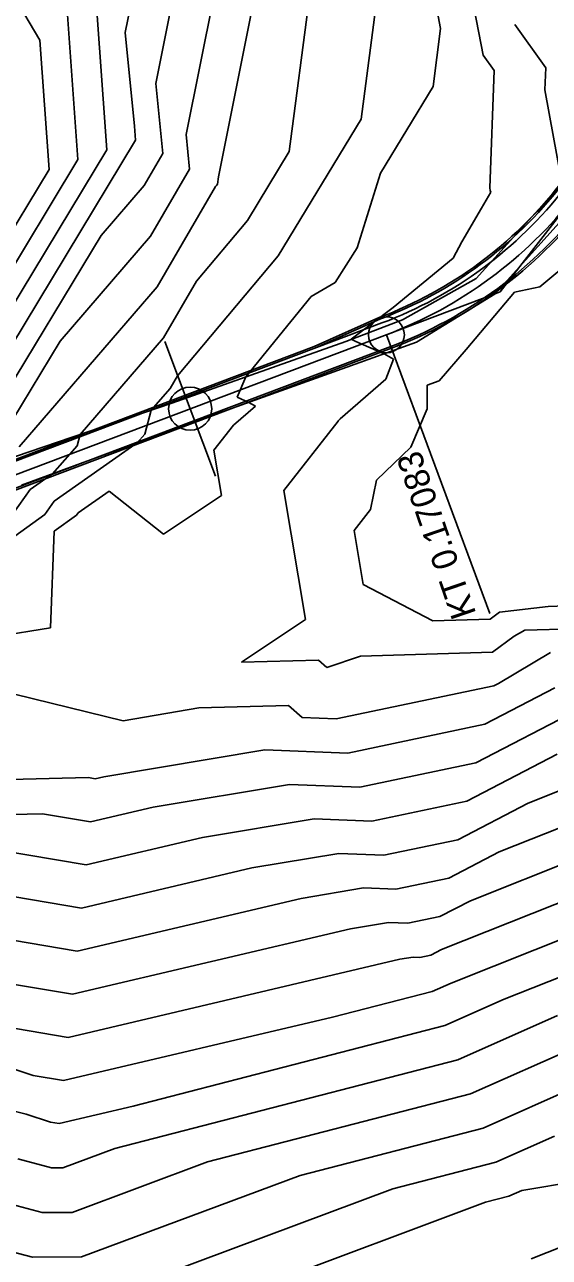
# Model space of a CAD drawing. Extents: x -549394 to -546608, y -1037055 to -1033629.
# Drawn here: x -547813.1 to -547740.1, y -1035648 to -1035476.6 of the extents above; entities that cross this region are included whole.
import ezdxf

# ---------------------------------------------------------------- set-up
doc = ezdxf.new("R2010")
doc.units = 0
for name, color, linetype in [('hlavni_vrst', 7, 'Continuous'), ('hrana_L', 7, 'Continuous'), ('norm_vrst', 7, 'Continuous'), ('POLYGONY_SITUACE_PO', 7, 'Continuous'), ('u_sirka_1_0m', 7, 'Continuous'), ('x_navrh_C11', 7, 'Continuous'), ('x_osa_C11', 7, 'Continuous'), ('x_popis_oblouky_C11', 7, 'Continuous'), ('x_popis_pricne_rezy_C11', 7, 'Continuous')]:
    doc.layers.add(name, color=color, linetype=linetype)

msp = doc.modelspace()

# ---------------------------------------------------------------- linework, layer by layer
at = {"layer": 'hlavni_vrst'}
for p, q in [((-547790.65, -1035491.85), (-547783.83, -1035457.7)), ((-547811, -1035478.7), (-547823.09, -1035458.32)), ((-547749.32, -1035480.8), (-547751.45, -1035469.69)), ((-547809.72, -1035496.69), (-547811, -1035478.7)), ((-547747.81, -1035482.91), (-547749.32, -1035480.8)), ((-547748.4, -1035499.26), (-547747.81, -1035482.91)), ((-547790.17, -1035496.66), (-547790.65, -1035491.85)), ((-547824.74, -1035521.56), (-547809.72, -1035496.69)), ((-547795.6, -1035505.97), (-547790.17, -1035496.66)), ((-547748.33, -1035499.63), (-547748.4, -1035499.26)), ((-547749.57, -1035502.06), (-547748.25, -1035499.85)), ((-547748.25, -1035499.85), (-547748.33, -1035499.63)), ((-547752.3, -1035506.77), (-547749.57, -1035502.06)), ((-547808.19, -1035520.58), (-547795.6, -1035505.97)), ((-547753.52, -1035509.03), (-547752.3, -1035506.77)), ((-547761.86, -1035515.87), (-547753.52, -1035509.03)), ((-547767.68, -1035520.31), (-547761.86, -1035515.87)), ((-547816.24, -1035533.92), (-547808.19, -1035520.58)), ((-547767.04, -1035520.62), (-547767.68, -1035520.31)), ((-547763.11, -1035522.34), (-547767.04, -1035520.62)), ((-547761.78, -1035523.07), (-547763.11, -1035522.34)), ((-547762.85, -1035525.84), (-547761.78, -1035523.07)), ((-547769.24, -1035531.38), (-547762.85, -1035525.84)), ((-547777.04, -1035541.33), (-547769.48, -1035531.68)), ((-547769.48, -1035531.68), (-547769.46, -1035531.6)), ((-547769.46, -1035531.6), (-547769.24, -1035531.38)), ((-547774.03, -1035559.28), (-547777.04, -1035541.33)), ((-547782.94, -1035565.21), (-547774.03, -1035559.28)), ((-547743.54, -1035560.76), (-547744.99, -1035561.61)), ((-547736.73, -1035560.59), (-547743.54, -1035560.76)), ((-547744.99, -1035561.61), (-547748.04, -1035563.85)), ((-547766.41, -1035564.39), (-547771.06, -1035565.95)), ((-547748.04, -1035563.85), (-547766.41, -1035564.39)), ((-547772.23, -1035564.94), (-547782.94, -1035565.21)), ((-547771.06, -1035565.95), (-547772.23, -1035564.94)), ((-547733.09, -1035580.87), (-547743.07, -1035584.83)), ((-547743.07, -1035584.83), (-547752.85, -1035589.91)), ((-547752.85, -1035589.91), (-547763.14, -1035592.07)), ((-547769.4, -1035591.83), (-547781.52, -1035593.85)), ((-547763.14, -1035592.07), (-547769.4, -1035591.83)), ((-547781.52, -1035593.85), (-547805.21, -1035599.43)), ((-547805.21, -1035599.43), (-547821.72, -1035596.64)), ((-547731.51, -1035606.21), (-547746.38, -1035612.11)), ((-547746.38, -1035612.11), (-547754.65, -1035615.77)), ((-547754.65, -1035615.77), (-547798.04, -1035626.99)), ((-547812.93, -1035628.1), (-547830.53, -1035623.58)), ((-547798.04, -1035626.99), (-547808.34, -1035629.41)), ((-547809.51, -1035629.21), (-547812.93, -1035628.1)), ((-547808.34, -1035629.41), (-547809.51, -1035629.21)), ((-547719.52, -1035634.57), (-547743.94, -1035638.7)), ((-547745.77, -1035639.51), (-547748.99, -1035640.35)), ((-547743.94, -1035638.7), (-547745.77, -1035639.51)), ((-547748.99, -1035640.35), (-547794.29, -1035657.24))]:
    msp.add_line(p, q, dxfattribs=at)
at = {"layer": 'hrana_L'}
for p, q in [((-547742.1, -1035502.76), (-547737.85, -1035498.19)), ((-547747.65, -1035514.01), (-547735.19, -1035500.12)), ((-547742.1, -1035502.76), (-547750.28, -1035511.84)), ((-547750.28, -1035511.84), (-547760.56, -1035517.59)), ((-547758.6, -1035520.72), (-547747.65, -1035514.01)), ((-547760.56, -1035517.59), (-547768.45, -1035520.6)), ((-547768.45, -1035520.6), (-547792.64, -1035529.21)), ((-547792.07, -1035532.74), (-547758.6, -1035520.72)), ((-547814.39, -1035536.61), (-547792.64, -1035529.21)), ((-547813.58, -1035540.62), (-547792.07, -1035532.74))]:
    msp.add_line(p, q, dxfattribs=at)
at = {"layer": 'norm_vrst'}
for p, q in [((-547776.3, -1035494.2), (-547770.68, -1035451.11)), ((-547786.17, -1035497.73), (-547777.32, -1035453.46)), ((-547794.89, -1035484.75), (-547790.33, -1035461.94)), ((-547755.25, -1035477.11), (-547757.91, -1035463.26)), ((-547766.3, -1035489.69), (-547762.97, -1035464.11)), ((-547799.13, -1035477.64), (-547796.84, -1035466.18)), ((-547801.69, -1035493.96), (-547803.35, -1035470.67)), ((-547805.71, -1035495.32), (-547807.19, -1035474.56)), ((-547740.62, -1035482.57), (-547744.92, -1035476.55)), ((-547797.82, -1035490.68), (-547799.13, -1035477.64)), ((-547756.3, -1035485.17), (-547755.25, -1035477.11)), ((-547740.73, -1035485.63), (-547740.62, -1035482.57)), ((-547793.91, -1035494.47), (-547794.89, -1035484.75)), ((-547763.62, -1035497.22), (-547756.3, -1035485.17)), ((-547738.44, -1035498.27), (-547740.73, -1035485.63)), ((-547797.68, -1035492.6), (-547797.82, -1035490.68)), ((-547777.85, -1035508.7), (-547766.3, -1035489.69)), ((-547821.34, -1035526.5), (-547801.69, -1035493.96)), ((-547819.64, -1035528.97), (-547797.68, -1035492.6)), ((-547782.13, -1035503.8), (-547776.3, -1035494.2)), ((-547823.04, -1035524.03), (-547805.71, -1035495.32)), ((-547796.5, -1035498.91), (-547793.91, -1035494.47)), ((-547766.88, -1035507.59), (-547763.62, -1035497.22)), ((-547802.5, -1035505.87), (-547796.5, -1035498.91)), ((-547794.7, -1035513.03), (-547786.55, -1035499.07)), ((-547786.55, -1035499.07), (-547786.41, -1035498.91)), ((-547786.41, -1035498.91), (-547786.3, -1035498.72)), ((-547786.3, -1035498.72), (-547786.17, -1035497.73)), ((-547789.21, -1035512.23), (-547782.13, -1035503.8)), ((-547817.94, -1035531.44), (-547802.5, -1035505.87)), ((-547769.91, -1035512.42), (-547766.88, -1035507.59)), ((-547791.87, -1035525.39), (-547777.85, -1035508.7)), ((-547741.46, -1035513.02), (-547738.65, -1035510.72)), ((-547813.88, -1035535.29), (-547794.7, -1035513.03)), ((-547793.8, -1035520.1), (-547789.21, -1035512.23)), ((-547773.24, -1035514.34), (-547769.91, -1035512.42)), ((-547744.97, -1035513.78), (-547741.46, -1035513.02)), ((-547782.36, -1035525.55), (-547773.24, -1035514.34)), ((-547751.7, -1035521.73), (-547744.97, -1035513.78)), ((-547805.39, -1035533.55), (-547793.8, -1035520.1)), ((-547755.46, -1035526.11), (-547751.7, -1035521.73)), ((-547792.9, -1035527.16), (-547791.87, -1035525.39)), ((-547783.57, -1035528.37), (-547782.36, -1035525.55)), ((-547757.14, -1035526.68), (-547755.46, -1035526.11)), ((-547757.11, -1035529.99), (-547757.14, -1035526.68)), ((-547795.51, -1035530.19), (-547792.9, -1035527.16)), ((-547781.92, -1035529.09), (-547783.57, -1035528.37)), ((-547796.4, -1035533.49), (-547795.51, -1035530.19)), ((-547784.08, -1035532.27), (-547780.99, -1035529.6)), ((-547780.99, -1035529.6), (-547781.92, -1035529.09)), ((-547759.4, -1035535.33), (-547757.11, -1035529.99)), ((-547805.82, -1035535.12), (-547805.39, -1035533.55)), ((-547797.48, -1035534.72), (-547796.4, -1035533.49)), ((-547786.8, -1035535.75), (-547784.08, -1035532.27)), ((-547809.23, -1035539.03), (-547805.82, -1035535.12)), ((-547809.01, -1035542.84), (-547797.48, -1035534.72)), ((-547764.16, -1035539.9), (-547759.4, -1035535.33)), ((-547785.74, -1035542.05), (-547786.8, -1035535.75)), ((-547812.35, -1035541.22), (-547809.23, -1035539.03)), ((-547765, -1035544.01), (-547764.16, -1035539.9)), ((-547814.73, -1035544.55), (-547812.35, -1035541.22)), ((-547805.68, -1035544.47), (-547801.37, -1035541.43)), ((-547801.37, -1035541.43), (-547793.79, -1035547.41)), ((-547793.79, -1035547.41), (-547785.74, -1035542.05)), ((-547810.32, -1035544.67), (-547809.01, -1035542.84)), ((-547821.28, -1035552.58), (-547810.32, -1035544.67)), ((-547809.01, -1035547.02), (-547805.91, -1035544.79)), ((-547805.91, -1035544.79), (-547805.68, -1035544.47)), ((-547767.28, -1035546.91), (-547765, -1035544.01)), ((-547809.54, -1035560.47), (-547809.01, -1035547.02)), ((-547766.02, -1035554.41), (-547767.28, -1035546.91)), ((-547756.31, -1035559.46), (-547766.02, -1035554.41)), ((-547740.3, -1035557.46), (-547747.06, -1035558.29)), ((-547737.81, -1035557.4), (-547740.3, -1035557.46)), ((-547748.34, -1035559.23), (-547756.31, -1035559.46)), ((-547747.06, -1035558.29), (-547748.34, -1035559.23)), ((-547824.52, -1035562.85), (-547809.54, -1035560.47)), ((-547739.94, -1035563.89), (-547747.21, -1035568.18)), ((-547799.43, -1035573.39), (-547821.16, -1035568.08)), ((-547747.85, -1035568.51), (-547769.8, -1035573.12)), ((-547739.33, -1035568.79), (-547749.1, -1035573.86)), ((-547747.21, -1035568.18), (-547747.85, -1035568.51)), ((-547776.43, -1035571.27), (-547788.87, -1035571.59)), ((-547774.49, -1035572.94), (-547776.43, -1035571.27)), ((-547735.03, -1035571.26), (-547750.35, -1035579.21)), ((-547788.87, -1035571.59), (-547799.43, -1035573.39)), ((-547769.8, -1035573.12), (-547774.49, -1035572.94)), ((-547749.1, -1035573.86), (-547768.14, -1035577.86)), ((-547779.72, -1035577.42), (-547802.13, -1035581.16)), ((-547768.14, -1035577.86), (-547779.72, -1035577.42)), ((-547739.05, -1035578.04), (-547751.6, -1035584.56)), ((-547750.35, -1035579.21), (-547766.47, -1035582.59)), ((-547804.25, -1035581.28), (-547834.2, -1035582)), ((-547803.33, -1035581.44), (-547804.25, -1035581.28)), ((-547802.13, -1035581.16), (-547803.33, -1035581.44)), ((-547776.28, -1035582.22), (-547795.26, -1035585.39)), ((-547766.47, -1035582.59), (-547776.28, -1035582.22)), ((-547751.6, -1035584.56), (-547764.81, -1035587.33)), ((-547810.63, -1035586.31), (-547829.92, -1035586.77)), ((-547803.96, -1035587.44), (-547810.63, -1035586.31)), ((-547795.26, -1035585.39), (-547803.96, -1035587.44)), ((-547732.77, -1035585.94), (-547747.09, -1035591.62)), ((-547772.84, -1035587.03), (-547788.39, -1035589.62)), ((-547764.81, -1035587.33), (-547772.84, -1035587.03)), ((-547788.39, -1035589.62), (-547804.58, -1035593.43)), ((-547804.58, -1035593.43), (-547817.01, -1035591.33)), ((-547747.09, -1035591.62), (-547754.1, -1035595.26)), ((-547732.46, -1035591.01), (-547751.11, -1035598.41)), ((-547754.1, -1035595.26), (-547761.47, -1035596.8)), ((-547765.96, -1035596.63), (-547774.64, -1035598.08)), ((-547761.47, -1035596.8), (-547765.96, -1035596.63)), ((-547732.14, -1035596.08), (-547755.13, -1035605.19)), ((-547774.64, -1035598.08), (-547805.84, -1035605.43)), ((-547751.11, -1035598.41), (-547755.35, -1035600.61)), ((-547762.52, -1035601.44), (-547767.77, -1035602.32)), ((-547759.81, -1035601.54), (-547762.52, -1035601.44)), ((-547755.35, -1035600.61), (-547759.81, -1035601.54)), ((-547731.82, -1035601.14), (-547753.78, -1035609.85)), ((-547805.84, -1035605.43), (-547819.27, -1035603.15)), ((-547767.77, -1035602.32), (-547806.46, -1035611.42)), ((-547755.13, -1035605.19), (-547756.6, -1035605.96)), ((-547760.9, -1035606.55), (-547807.09, -1035617.42)), ((-547759.08, -1035606.24), (-547760.9, -1035606.55)), ((-547758.14, -1035606.28), (-547759.08, -1035606.24)), ((-547756.6, -1035605.96), (-547758.14, -1035606.28)), ((-547806.46, -1035611.42), (-547816.83, -1035609.67)), ((-547753.78, -1035609.85), (-547756.42, -1035611.02)), ((-547756.42, -1035611.02), (-547770.3, -1035614.61)), ((-547770.3, -1035614.61), (-547807.72, -1035623.41)), ((-547738.98, -1035614.37), (-547752.87, -1035620.52)), ((-547807.09, -1035617.42), (-547814.39, -1035616.18)), ((-547731.58, -1035616.62), (-547751.1, -1035625.27)), ((-547811.95, -1035622.7), (-547824.38, -1035618.66)), ((-547752.87, -1035620.52), (-547800.58, -1035632.85)), ((-547807.72, -1035623.41), (-547811.95, -1035622.7)), ((-547734.91, -1035623.63), (-547749.32, -1035630.02)), ((-547751.1, -1035625.27), (-547787.68, -1035634.73)), ((-547749.32, -1035630.02), (-547774.79, -1035636.6)), ((-547739.42, -1035631.17), (-547747.54, -1035634.76)), ((-547800.58, -1035632.85), (-547807.79, -1035635.54)), ((-547809.39, -1035635.54), (-547814.08, -1035634.31)), ((-547787.68, -1035634.73), (-547806.51, -1035641.75)), ((-547747.54, -1035634.76), (-547761.89, -1035638.47)), ((-547807.79, -1035635.54), (-547809.39, -1035635.54)), ((-547774.79, -1035636.6), (-547805.23, -1035647.95)), ((-547810.7, -1035641.76), (-547822.95, -1035638.53)), ((-547761.89, -1035638.47), (-547803.95, -1035654.16)), ((-547812.01, -1035647.98), (-547831.81, -1035642.75)), ((-547806.51, -1035641.75), (-547810.7, -1035641.76)), ((-547729.59, -1035643.04), (-547742.66, -1035648.19)), ((-547805.23, -1035647.95), (-547812.01, -1035647.98))]:
    msp.add_line(p, q, dxfattribs=at)
at = {"layer": 'POLYGONY_SITUACE_PO'}
msp.add_circle((-547762.79, -1035519.68), 2.5, dxfattribs=at)
at = {"layer": 'u_sirka_1_0m'}
msp.add_circle((-547790.09, -1035529.97), 3, dxfattribs=at)
at = {"layer": 'x_navrh_C11'}
for p, q in [((-547763.41, -1035518.04), (-547833.94, -1035544.64)), ((-547763.72, -1035517.25), (-547772.86, -1035521.34)), ((-547763.62, -1035517.48), (-547772.77, -1035521.57)), ((-547762.18, -1035521.32), (-547832.71, -1035547.91)), ((-547772.86, -1035521.34), (-547824.66, -1035540.87)), ((-547762.09, -1035521.55), (-547820.66, -1035543.64))]:
    msp.add_line(p, q, dxfattribs=at)
for radius, start in [(57.4, 290.6532), (57.65, 290.6607), (58.25, 290.6607), (61.75, 290.6607), (62, 290.6607)]:
    msp.add_arc((-547783.96, -1035463.54), radius, start, 322.1652, dxfattribs=at)
at = {"layer": 'x_osa_C11'}
for points in [[(-547696.57, -1035442.62), (-547714.94, -1035472.48), (-547746.96, -1035513.71)], [(-547746.96, -1035513.71), (-547845.9, -1035551.02)]]:
    msp.add_lwpolyline(points, dxfattribs=at)
msp.add_arc((-547783.96, -1035463.54), 60, 290.6607, 322.1652, dxfattribs=at)
at = {"layer": 'x_popis_oblouky_C11'}
msp.add_lwpolyline([(-547762.79, -1035519.68), (-547748.42, -1035558.47)], dxfattribs=at)
at = {"layer": 'x_popis_pricne_rezy_C11'}
msp.add_lwpolyline([(-547786.56, -1035539.33), (-547790.09, -1035529.97), (-547793.62, -1035520.61)], dxfattribs=at)

# ---------------------------------------------------------------- texts
at = {"layer": 'x_popis_oblouky_C11'}
msp.add_text('KT 0.17083', height=3.5, rotation=108.9562, dxfattribs=at).set_placement((-547750.27, -1035558.47))

doc.saveas('drawing.dxf')
